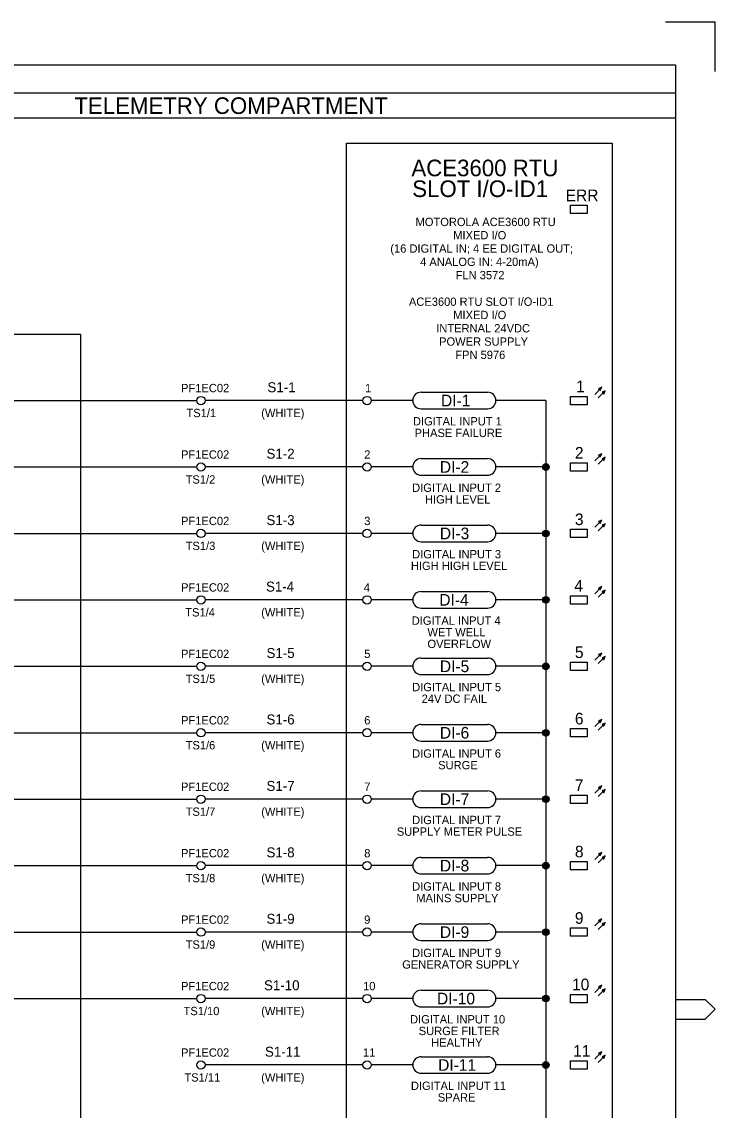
# Model space of a CAD drawing. Extents: x 0 to 841, y 0 to 594.
# Drawn here: x 632.3 to 841, y 266.4 to 594 of the extents above; entities that cross this region are included whole.
import ezdxf

# ---------------------------------------------------------------- set-up
doc = ezdxf.new("R2010")
doc.units = 0
for name, color, linetype in [('A1BORDER', 7, 'Continuous'), ('BASE', 7, 'Continuous'), ('Level 1', 7, 'Continuous'), ('Level 10', 7, 'Continuous')]:
    doc.layers.add(name, color=color, linetype=linetype)

msp = doc.modelspace()

# ---------------------------------------------------------------- linework, layer by layer
at = {"layer": 'A1BORDER'}
for p, q in [((826, 594), (841, 594)), ((841, 579), (841, 594)), ((28, 581), (829, 581)), ((829, 581), (829, 15)), ((829, 299.76), (838, 299.76)), ((838, 299.76), (841, 296.76)), ((838, 293.76), (841, 296.76)), ((829, 293.76), (838, 293.76))]:
    msp.add_line(p, q, dxfattribs=at)
at = {"layer": 'BASE'}
msp.add_line((507.5, 360), (685, 360), dxfattribs=at)
at = {"layer": 'Level 1'}
for p, q in [((829, 572.5), (160, 572.5)), ((829, 565), (160, 565)), ((610, 500), (650, 500)), ((650, 500), (650, 160)), ((752.5, 482.5), (772.5, 482.5)), ((370, 480), (685, 480)), ((735, 480), (687.5, 480)), ((750, 480), (737.5, 480)), ((790, 480), (775, 480)), ((790, 480), (790, 140)), ((752.5, 477.5), (772.5, 477.5)), ((752.5, 462.5), (772.5, 462.5)), ((270, 460), (685, 460)), ((735, 460), (687.5, 460)), ((750, 460), (737.5, 460)), ((790, 460), (775, 460)), ((752.5, 457.5), (772.5, 457.5)), ((752.5, 442.5), (772.5, 442.5)), ((270, 440), (685, 440)), ((735, 440), (687.5, 440)), ((750, 440), (737.5, 440)), ((790, 440), (775, 440)), ((752.5, 437.5), (772.5, 437.5)), ((270, 420), (685, 420)), ((735, 420), (687.5, 420)), ((750, 420), (737.5, 420)), ((752.5, 422.5), (772.5, 422.5)), ((790, 420), (775, 420)), ((752.5, 417.5), (772.5, 417.5)), ((370, 400), (685, 400)), ((735, 400), (687.5, 400)), ((750, 400), (737.5, 400)), ((752.5, 402.5), (772.5, 402.5)), ((790, 400), (775, 400)), ((752.5, 397.5), (772.5, 397.5)), ((752.5, 382.5), (772.5, 382.5)), ((410, 380), (685, 380)), ((735, 380), (687.5, 380)), ((750, 380), (737.5, 380)), ((752.5, 377.5), (772.5, 377.5)), ((790, 380), (775, 380)), ((752.5, 362.5), (772.5, 362.5)), ((735, 360), (687.5, 360)), ((750, 360), (737.5, 360)), ((752.5, 357.5), (772.5, 357.5)), ((790, 360), (775, 360)), ((752.5, 342.5), (772.5, 342.5)), ((500, 340), (685, 340)), ((735, 340), (687.5, 340)), ((750, 340), (737.5, 340)), ((752.5, 337.5), (772.5, 337.5)), ((790, 340), (775, 340)), ((752.5, 322.5), (772.5, 322.5)), ((500, 320), (685, 320)), ((735, 320), (687.5, 320)), ((750, 320), (737.5, 320)), ((790, 320), (775, 320)), ((752.5, 317.5), (772.5, 317.5)), ((752.5, 302.5), (772.5, 302.5)), ((520, 300), (685, 300)), ((735, 300), (687.5, 300)), ((750, 300), (737.5, 300)), ((790, 300), (775, 300)), ((752.5, 297.5), (772.5, 297.5)), ((752.5, 282.5), (772.5, 282.5)), ((735, 280), (687.5, 280)), ((750, 280), (737.5, 280)), ((790, 280), (775, 280)), ((752.5, 277.5), (772.5, 277.5))]:
    msp.add_line(p, q, dxfattribs=at)
msp.add_lwpolyline([(730, 96.05), (730, 557.5), (810, 557.5), (810, 103.95)], dxfattribs=at)
for points in [[(797.5, 538.75), (802.5, 538.75), (802.5, 536.25), (797.5, 536.25)], [(797.5, 481.25), (802.5, 481.25), (802.5, 478.75), (797.5, 478.75)], [(797.5, 461.25), (802.5, 461.25), (802.5, 458.75), (797.5, 458.75)], [(797.5, 441.25), (802.5, 441.25), (802.5, 438.75), (797.5, 438.75)], [(797.5, 421.25), (802.5, 421.25), (802.5, 418.75), (797.5, 418.75)], [(797.5, 401.25), (802.5, 401.25), (802.5, 398.75), (797.5, 398.75)], [(797.5, 381.25), (802.5, 381.25), (802.5, 378.75), (797.5, 378.75)], [(797.5, 361.25), (802.5, 361.25), (802.5, 358.75), (797.5, 358.75)], [(797.5, 341.25), (802.5, 341.25), (802.5, 338.75), (797.5, 338.75)], [(797.5, 321.25), (802.5, 321.25), (802.5, 318.75), (797.5, 318.75)], [(797.5, 301.25), (802.5, 301.25), (802.5, 298.75), (797.5, 298.75)], [(797.5, 281.25), (802.5, 281.25), (802.5, 278.75), (797.5, 278.75)]]:
    msp.add_lwpolyline(points, close=True, dxfattribs=at)
for centre, start, end in [((752.5, 480), 90, 270), ((772.5, 480), 270, 90), ((752.5, 460), 90, 270), ((772.5, 460), 270, 90), ((752.5, 440), 90, 270), ((772.5, 440), 270, 90), ((752.5, 420), 90, 270), ((772.5, 420), 270, 90), ((752.5, 400), 90, 270), ((772.5, 400), 270, 90), ((752.5, 380), 90, 270), ((772.5, 380), 270, 90), ((752.5, 360), 90, 270), ((772.5, 360), 270, 90), ((752.5, 340), 90, 270), ((772.5, 340), 270, 90), ((752.5, 320), 90, 270), ((772.5, 320), 270, 90), ((752.5, 300), 90, 270), ((772.5, 300), 270, 90), ((752.5, 280), 90, 270), ((772.5, 280), 270, 90)]:
    msp.add_arc(centre, 2.5, start, end, dxfattribs=at)
at = {"layer": 'Level 10'}
for p, q in [((804.73, 481.86), (806.86, 483.98)), ((805.79, 480.8), (807.91, 482.92)), ((805.96, 483.58), (806.67, 483.58)), ((806, 483.43), (806.61, 483.43)), ((806.14, 483.28), (806.53, 483.28)), ((806.29, 483.73), (806.74, 483.73)), ((806.3, 483.13), (806.47, 483.13)), ((806.62, 483.88), (806.81, 483.88)), ((807.02, 482.52), (807.73, 482.52)), ((807.06, 482.37), (807.66, 482.37)), ((807.21, 482.22), (807.6, 482.22)), ((807.35, 482.67), (807.8, 482.67)), ((807.36, 482.07), (807.53, 482.07)), ((807.68, 482.82), (807.87, 482.82)), ((804.73, 461.86), (806.86, 463.98)), ((805.79, 460.8), (807.91, 462.92)), ((805.96, 463.58), (806.67, 463.58)), ((806, 463.43), (806.61, 463.43)), ((806.14, 463.28), (806.53, 463.28)), ((806.29, 463.73), (806.74, 463.73)), ((806.3, 463.13), (806.47, 463.13)), ((806.62, 463.88), (806.81, 463.88)), ((807.02, 462.52), (807.73, 462.52)), ((807.06, 462.37), (807.66, 462.37)), ((807.21, 462.22), (807.6, 462.22)), ((807.35, 462.67), (807.8, 462.67)), ((807.36, 462.07), (807.53, 462.07)), ((807.68, 462.82), (807.87, 462.82)), ((789.01, 460.1), (790.99, 460.1)), ((789.02, 459.8), (790.98, 459.8)), ((789.08, 460.4), (790.92, 460.4)), ((789.13, 459.5), (790.87, 459.5)), ((789.29, 460.7), (790.71, 460.7)), ((789.4, 459.2), (790.6, 459.2)), ((790, 461), (790, 461)), ((804.73, 441.86), (806.86, 443.98)), ((805.79, 440.8), (807.91, 442.92)), ((805.96, 443.58), (806.67, 443.58)), ((806, 443.43), (806.61, 443.43)), ((806.14, 443.28), (806.53, 443.28)), ((806.29, 443.73), (806.74, 443.73)), ((806.3, 443.13), (806.47, 443.13)), ((806.62, 443.88), (806.81, 443.88)), ((807.02, 442.52), (807.73, 442.52)), ((807.06, 442.37), (807.66, 442.37)), ((807.35, 442.67), (807.8, 442.67)), ((807.68, 442.82), (807.87, 442.82)), ((789.01, 440.1), (790.99, 440.1)), ((789.02, 439.8), (790.98, 439.8)), ((789.08, 440.4), (790.92, 440.4)), ((789.13, 439.5), (790.87, 439.5)), ((789.29, 440.7), (790.71, 440.7)), ((789.4, 439.2), (790.6, 439.2)), ((790, 441), (790, 441)), ((807.21, 442.22), (807.6, 442.22)), ((807.36, 442.07), (807.53, 442.07)), ((804.73, 421.86), (806.86, 423.98)), ((805.79, 420.8), (807.91, 422.92)), ((805.96, 423.58), (806.67, 423.58)), ((806, 423.43), (806.61, 423.43)), ((806.14, 423.28), (806.53, 423.28)), ((806.29, 423.73), (806.74, 423.73)), ((806.3, 423.13), (806.47, 423.13)), ((806.62, 423.88), (806.81, 423.88)), ((807.35, 422.67), (807.8, 422.67)), ((807.68, 422.82), (807.87, 422.82)), ((789.01, 420.1), (790.99, 420.1)), ((789.02, 419.8), (790.98, 419.8)), ((789.08, 420.4), (790.92, 420.4)), ((789.13, 419.5), (790.87, 419.5)), ((789.29, 420.7), (790.71, 420.7)), ((790, 421), (790, 421)), ((807.02, 422.52), (807.73, 422.52)), ((807.06, 422.37), (807.66, 422.37)), ((807.21, 422.22), (807.6, 422.22)), ((807.36, 422.07), (807.53, 422.07)), ((789.4, 419.2), (790.6, 419.2)), ((804.73, 401.86), (806.86, 403.98)), ((805.96, 403.58), (806.67, 403.58)), ((806, 403.43), (806.61, 403.43)), ((806.14, 403.28), (806.53, 403.28)), ((806.29, 403.73), (806.74, 403.73)), ((806.3, 403.13), (806.47, 403.13)), ((806.62, 403.88), (806.81, 403.88)), ((789.01, 400.1), (790.99, 400.1)), ((789.02, 399.8), (790.98, 399.8)), ((789.08, 400.4), (790.92, 400.4)), ((789.29, 400.7), (790.71, 400.7)), ((790, 401), (790, 401)), ((805.79, 400.8), (807.91, 402.92)), ((807.02, 402.52), (807.73, 402.52)), ((807.06, 402.37), (807.66, 402.37)), ((807.21, 402.22), (807.6, 402.22)), ((807.35, 402.67), (807.8, 402.67)), ((807.36, 402.07), (807.53, 402.07)), ((807.68, 402.82), (807.87, 402.82)), ((789.13, 399.5), (790.87, 399.5)), ((789.4, 399.2), (790.6, 399.2)), ((804.73, 381.86), (806.86, 383.98)), ((805.96, 383.58), (806.67, 383.58)), ((806, 383.43), (806.61, 383.43)), ((806.29, 383.73), (806.74, 383.73)), ((806.62, 383.88), (806.81, 383.88)), ((789.01, 380.1), (790.99, 380.1)), ((789.08, 380.4), (790.92, 380.4)), ((789.29, 380.7), (790.71, 380.7)), ((790, 381), (790, 381)), ((805.79, 380.8), (807.91, 382.92)), ((806.14, 383.28), (806.53, 383.28)), ((806.3, 383.13), (806.47, 383.13)), ((807.02, 382.52), (807.73, 382.52)), ((807.06, 382.37), (807.66, 382.37)), ((807.21, 382.22), (807.6, 382.22)), ((807.35, 382.67), (807.8, 382.67)), ((807.36, 382.07), (807.53, 382.07)), ((807.68, 382.82), (807.87, 382.82)), ((789.02, 379.8), (790.98, 379.8)), ((789.13, 379.5), (790.87, 379.5)), ((789.4, 379.2), (790.6, 379.2)), ((804.73, 361.86), (806.86, 363.98)), ((806.29, 363.73), (806.74, 363.73)), ((806.62, 363.88), (806.81, 363.88)), ((789.08, 360.4), (790.92, 360.4)), ((789.29, 360.7), (790.71, 360.7)), ((790, 361), (790, 361)), ((805.79, 360.8), (807.91, 362.92)), ((805.96, 363.58), (806.67, 363.58)), ((806, 363.43), (806.61, 363.43)), ((806.14, 363.28), (806.53, 363.28)), ((806.3, 363.13), (806.47, 363.13)), ((807.02, 362.52), (807.73, 362.52)), ((807.06, 362.37), (807.66, 362.37)), ((807.21, 362.22), (807.6, 362.22)), ((807.35, 362.67), (807.8, 362.67)), ((807.36, 362.07), (807.53, 362.07)), ((807.68, 362.82), (807.87, 362.82)), ((789.01, 360.1), (790.99, 360.1)), ((789.02, 359.8), (790.98, 359.8)), ((789.13, 359.5), (790.87, 359.5)), ((789.4, 359.2), (790.6, 359.2)), ((790, 341), (790, 341)), ((804.73, 341.86), (806.86, 343.98)), ((805.79, 340.8), (807.91, 342.92)), ((805.96, 343.58), (806.67, 343.58)), ((806, 343.43), (806.61, 343.43)), ((806.14, 343.28), (806.53, 343.28)), ((806.29, 343.73), (806.74, 343.73)), ((806.3, 343.13), (806.47, 343.13)), ((806.62, 343.88), (806.81, 343.88)), ((807.02, 342.52), (807.73, 342.52)), ((807.06, 342.37), (807.66, 342.37)), ((807.21, 342.22), (807.6, 342.22)), ((807.35, 342.67), (807.8, 342.67)), ((807.36, 342.07), (807.53, 342.07)), ((807.68, 342.82), (807.87, 342.82)), ((789.01, 340.1), (790.99, 340.1)), ((789.02, 339.8), (790.98, 339.8)), ((789.08, 340.4), (790.92, 340.4)), ((789.13, 339.5), (790.87, 339.5)), ((789.29, 340.7), (790.71, 340.7)), ((789.4, 339.2), (790.6, 339.2)), ((804.73, 321.86), (806.86, 323.98)), ((805.79, 320.8), (807.91, 322.92)), ((805.96, 323.58), (806.67, 323.58)), ((806, 323.43), (806.61, 323.43)), ((806.14, 323.28), (806.53, 323.28)), ((806.29, 323.73), (806.74, 323.73)), ((806.3, 323.13), (806.47, 323.13)), ((806.62, 323.88), (806.81, 323.88)), ((807.02, 322.52), (807.73, 322.52)), ((807.06, 322.37), (807.66, 322.37)), ((807.21, 322.22), (807.6, 322.22)), ((807.35, 322.67), (807.8, 322.67)), ((807.36, 322.07), (807.53, 322.07)), ((807.68, 322.82), (807.87, 322.82)), ((789.01, 320.1), (790.99, 320.1)), ((789.02, 319.8), (790.98, 319.8)), ((789.08, 320.4), (790.92, 320.4)), ((789.13, 319.5), (790.87, 319.5)), ((789.29, 320.7), (790.71, 320.7)), ((789.4, 319.2), (790.6, 319.2)), ((790, 321), (790, 321)), ((804.73, 301.86), (806.86, 303.98)), ((805.79, 300.8), (807.91, 302.92)), ((805.96, 303.58), (806.67, 303.58)), ((806, 303.43), (806.61, 303.43)), ((806.14, 303.28), (806.53, 303.28)), ((806.29, 303.73), (806.74, 303.73)), ((806.3, 303.13), (806.47, 303.13)), ((806.62, 303.88), (806.81, 303.88)), ((807.02, 302.52), (807.73, 302.52)), ((807.06, 302.37), (807.66, 302.37)), ((807.21, 302.22), (807.6, 302.22)), ((807.35, 302.67), (807.8, 302.67)), ((807.36, 302.07), (807.53, 302.07)), ((807.68, 302.82), (807.87, 302.82)), ((789.01, 300.1), (790.99, 300.1)), ((789.02, 299.8), (790.98, 299.8)), ((789.08, 300.4), (790.92, 300.4)), ((789.13, 299.5), (790.87, 299.5)), ((789.29, 300.7), (790.71, 300.7)), ((789.4, 299.2), (790.6, 299.2)), ((790, 301), (790, 301)), ((804.73, 281.86), (806.86, 283.98)), ((805.79, 280.8), (807.91, 282.92)), ((805.96, 283.58), (806.67, 283.58)), ((806, 283.43), (806.61, 283.43)), ((806.14, 283.28), (806.53, 283.28)), ((806.29, 283.73), (806.74, 283.73)), ((806.3, 283.13), (806.47, 283.13)), ((806.62, 283.88), (806.81, 283.88)), ((807.02, 282.52), (807.73, 282.52)), ((807.06, 282.37), (807.66, 282.37)), ((807.21, 282.22), (807.6, 282.22)), ((807.35, 282.67), (807.8, 282.67)), ((807.36, 282.07), (807.53, 282.07)), ((807.68, 282.82), (807.87, 282.82)), ((789.01, 280.1), (790.99, 280.1)), ((789.02, 279.8), (790.98, 279.8)), ((789.08, 280.4), (790.92, 280.4)), ((789.13, 279.5), (790.87, 279.5)), ((789.29, 280.7), (790.71, 280.7)), ((789.4, 279.2), (790.6, 279.2)), ((790, 281), (790, 281))]:
    msp.add_line(p, q, dxfattribs=at)
for points in [[(806.86, 483.98), (805.88, 483.54), (806.41, 483.01)], [(807.91, 482.92), (806.94, 482.48), (807.48, 481.95)], [(806.86, 463.98), (805.88, 463.54), (806.41, 463.01)], [(807.91, 462.92), (806.94, 462.48), (807.48, 461.95)], [(806.86, 443.98), (805.88, 443.54), (806.41, 443.01)], [(807.91, 442.92), (806.94, 442.48), (807.48, 441.95)], [(806.86, 423.98), (805.88, 423.54), (806.41, 423.01)], [(807.91, 422.92), (806.94, 422.48), (807.48, 421.95)], [(806.86, 403.98), (805.88, 403.54), (806.41, 403.01)], [(807.91, 402.92), (806.94, 402.48), (807.48, 401.95)], [(806.86, 383.98), (805.88, 383.54), (806.41, 383.01)], [(807.91, 382.92), (806.94, 382.48), (807.48, 381.95)], [(806.86, 363.98), (805.88, 363.54), (806.41, 363.01)], [(807.91, 362.92), (806.94, 362.48), (807.48, 361.95)], [(806.86, 343.98), (805.88, 343.54), (806.41, 343.01)], [(807.91, 342.92), (806.94, 342.48), (807.48, 341.95)], [(806.86, 323.98), (805.88, 323.54), (806.41, 323.01)], [(807.91, 322.92), (806.94, 322.48), (807.48, 321.95)], [(806.86, 303.98), (805.88, 303.54), (806.41, 303.01)], [(807.91, 302.92), (806.94, 302.48), (807.48, 301.95)], [(806.86, 283.98), (805.88, 283.54), (806.41, 283.01)], [(807.91, 282.92), (806.94, 282.48), (807.48, 281.95)]]:
    msp.add_lwpolyline(points, close=True, dxfattribs=at)
for centre, radius in [((686.25, 480), 1.25), ((736.25, 480), 1.25), ((686.25, 460), 1.25), ((736.25, 460), 1.25), ((790, 460), 1), ((686.25, 440), 1.25), ((736.25, 440), 1.25), ((790, 440), 1), ((686.25, 420), 1.25), ((736.25, 420), 1.25), ((790, 420), 1), ((686.25, 400), 1.25), ((736.25, 400), 1.25), ((790, 400), 1), ((686.25, 380), 1.25), ((736.25, 380), 1.25), ((790, 380), 1), ((686.25, 360), 1.25), ((736.25, 360), 1.25), ((790, 360), 1), ((686.25, 340), 1.25), ((736.25, 340), 1.25), ((790, 340), 1), ((686.25, 320), 1.25), ((736.25, 320), 1.25), ((790, 320), 1), ((686.25, 300), 1.25), ((736.25, 300), 1.25), ((790, 300), 1), ((686.25, 280), 1.25), ((736.25, 280), 1.25), ((790, 280), 1)]:
    msp.add_circle(centre, radius, dxfattribs=at)

# ---------------------------------------------------------------- texts
at = {"layer": 'Level 1'}
for s, height, p in [('TELEMETRY COMPARTMENT', 5, (648.16, 566.25)), ('ACE3600 RTU', 5, (749.58, 547.5)), ('SLOT I/O-ID1', 5, (749.83, 541.25)), ('ERR', 3.5, (795.99, 540)), ('MOTOROLA ACE3600 RTU', 2.5, (750.83, 532.5)), ('MIXED I/O', 2.5, (762.16, 528.5)), ('(16 DIGITAL IN; 4 EE DIGITAL OUT; ', 2.5, (743.23, 524.5)), ('4 ANALOG IN: 4-20mA)', 2.5, (752.19, 520.5)), ('FLN 3572', 2.5, (762.9, 516.5)), ('ACE3600 RTU SLOT I/O-ID1', 2.5, (748.83, 508.5)), ('MIXED I/O', 2.5, (762.16, 504.5)), ('INTERNAL 24VDC', 2.5, (757.05, 500.5)), ('POWER SUPPLY', 2.5, (757.92, 496.5)), ('FPN 5976', 2.5, (762.78, 492.5)), ('PF1EC02', 2.5, (680.27, 482.5)), ('S1-1', 3, (706.26, 482.5)), ('1', 2.5, (735.63, 482.5)), ('1', 3.5, (799.13, 482.5)), ('DI-1', 3.5, (758.49, 478.25)), ('TS1/1', 2.5, (681.9, 475)), ('(WHITE)', 2.5, (704.39, 475)), ('DIGITAL INPUT 1', 2.5, (750.05, 472.5)), ('PHASE FAILURE', 2.5, (750.55, 469)), ('S1-2', 3, (705.97, 462.5)), ('2', 3.5, (798.78, 462.5)), ('PF1EC02', 2.5, (680.27, 462.5)), ('2', 2.5, (735.38, 462.5)), ('DI-2', 3.5, (758.14, 458.25)), ('TS1/2', 2.5, (681.65, 455)), ('(WHITE)', 2.5, (704.39, 455)), ('DIGITAL INPUT 2', 2.5, (749.8, 452.5)), ('HIGH LEVEL', 2.5, (753.66, 449)), ('3', 3.5, (798.78, 442.5)), ('PF1EC02', 2.5, (680.27, 442.5)), ('S1-3', 3, (705.97, 442.5)), ('3', 2.5, (735.38, 442.5)), ('DI-3', 3.5, (758.14, 438.25)), ('TS1/3', 2.5, (681.65, 435)), ('(WHITE)', 2.5, (704.39, 435)), ('DIGITAL INPUT 3', 2.5, (749.8, 432.5)), ('HIGH HIGH LEVEL', 2.5, (749.43, 429)), ('4', 3.5, (798.61, 422.5)), ('PF1EC02', 2.5, (680.27, 422.5)), ('S1-4', 3, (705.82, 422.5)), ('4', 2.5, (735.25, 422.5)), ('DI-4', 3.5, (757.97, 418.25)), ('TS1/4', 2.5, (681.53, 415)), ('(WHITE)', 2.5, (704.39, 415)), ('DIGITAL INPUT 4', 2.5, (749.68, 412.5)), ('WET WELL', 2.5, (754.41, 409)), ('OVERFLOW', 2.5, (754.41, 405.5)), ('PF1EC02', 2.5, (680.27, 402.5)), ('S1-5', 3, (705.97, 402.5)), ('5', 2.5, (735.38, 402.5)), ('5', 3.5, (798.78, 402.5)), ('DI-5', 3.5, (758.14, 398.25)), ('TS1/5', 2.5, (681.65, 395)), ('(WHITE)', 2.5, (704.39, 395)), ('DIGITAL INPUT 5', 2.5, (749.8, 392.5)), ('24V DC FAIL', 2.5, (752.66, 389)), ('PF1EC02', 2.5, (680.27, 382.5)), ('S1-6', 3, (705.97, 382.5)), ('6', 2.5, (735.38, 382.5)), ('6', 3.5, (798.78, 382.5)), ('DI-6', 3.5, (758.14, 378.25)), ('TS1/6', 2.5, (681.65, 375)), ('(WHITE)', 2.5, (704.39, 375)), ('DIGITAL INPUT 6', 2.5, (749.8, 372.5)), ('SURGE', 2.5, (757.64, 369)), ('PF1EC02', 2.5, (680.27, 362.5)), ('S1-7', 3, (705.97, 362.5)), ('7', 2.5, (735.38, 362.5)), ('7', 3.5, (798.78, 362.5)), ('DI-7', 3.5, (758.14, 358.25)), ('TS1/7', 2.5, (681.65, 355)), ('(WHITE)', 2.5, (704.39, 355)), ('DIGITAL INPUT 7', 2.5, (749.8, 352.5)), ('SUPPLY METER PULSE', 2.5, (745.19, 349)), ('PF1EC02', 2.5, (680.27, 342.5)), ('S1-8', 3, (705.97, 342.5)), ('8', 2.5, (735.38, 342.5)), ('8', 3.5, (798.78, 342.5)), ('DI-8', 3.5, (758.14, 338.25)), ('TS1/8', 2.5, (681.65, 335)), ('(WHITE)', 2.5, (704.39, 335)), ('DIGITAL INPUT 8', 2.5, (749.8, 332.5)), ('MAINS SUPPLY', 2.5, (751.04, 329)), ('PF1EC02', 2.5, (680.27, 322.5)), ('S1-9', 3, (705.97, 322.5)), ('9', 2.5, (735.38, 322.5)), ('9', 3.5, (798.78, 322.5)), ('DI-9', 3.5, (758.14, 318.25)), ('TS1/9', 2.5, (681.65, 315)), ('(WHITE)', 2.5, (704.39, 315)), ('DIGITAL INPUT 9', 2.5, (749.8, 312.5)), ('GENERATOR SUPPLY', 2.5, (746.81, 309)), ('PF1EC02', 2.5, (680.27, 302.5)), ('S1-10', 3, (705.22, 302.5)), ('10', 2.5, (735.05, 302.5)), ('10', 3.5, (797.91, 302.5)), ('DI-10', 3.5, (757.27, 298.25)), ('TS1/10', 2.5, (681.03, 295)), ('(WHITE)', 2.5, (704.39, 295)), ('DIGITAL INPUT 10', 2.5, (749.18, 292.5)), ('SURGE FILTER', 2.5, (751.79, 289)), ('PF1EC02', 2.5, (680.27, 282.5)), ('S1-11', 3, (705.52, 282.5)), ('HEALTHY', 2.5, (755.53, 285.5)), ('11', 3.5, (798.26, 282.5)), ('11', 2.5, (735.01, 282.5)), ('DI-11', 3.5, (757.62, 278.25)), ('TS1/11', 2.5, (681.28, 275)), ('(WHITE)', 2.5, (704.39, 275)), ('DIGITAL INPUT 11', 2.5, (749.43, 272.5)), ('SPARE', 2.5, (757.52, 269))]:
    msp.add_text(s, height=height, dxfattribs=at).set_placement(p)

doc.saveas('drawing.dxf')
